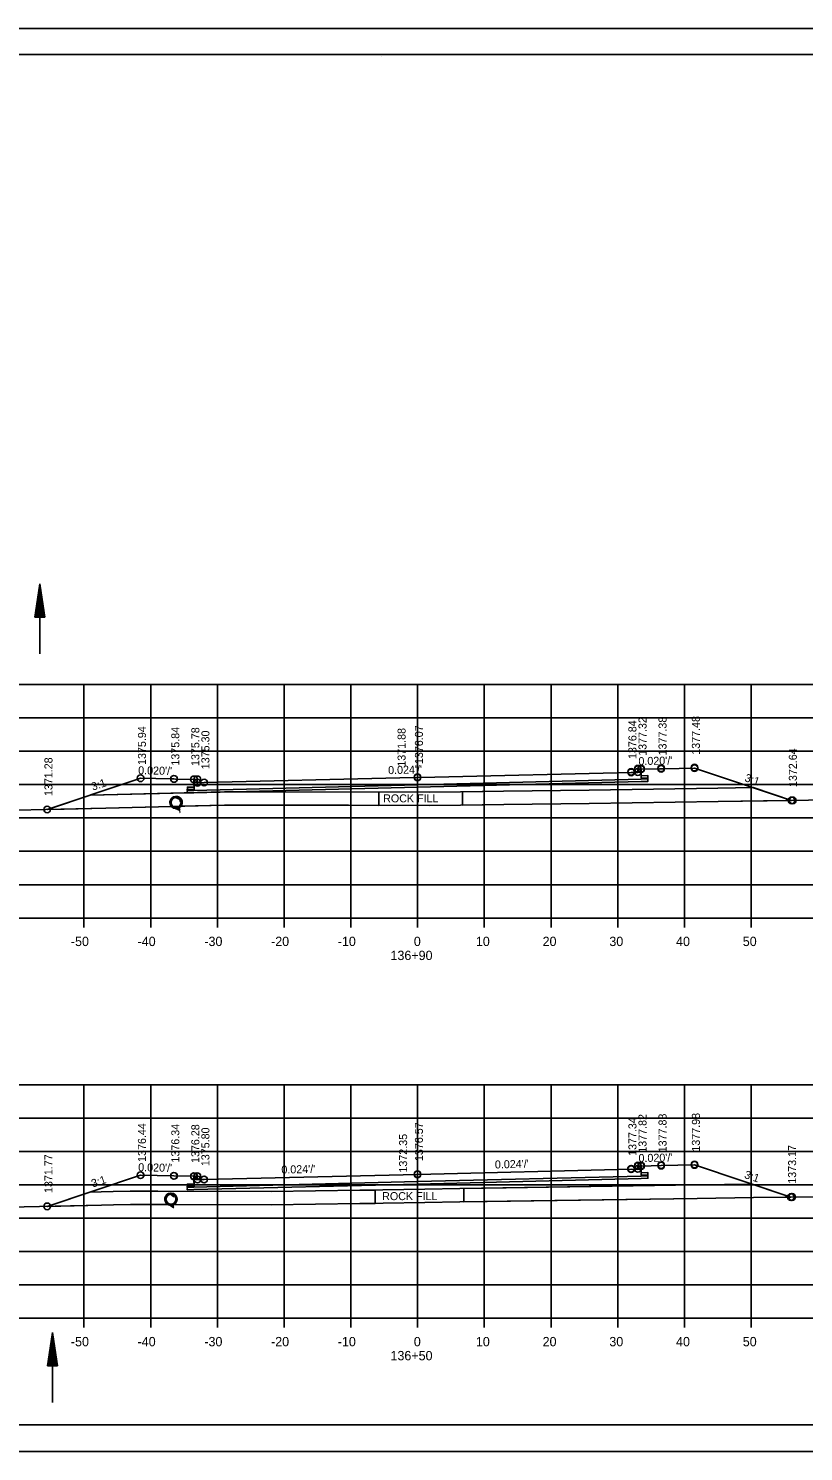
# Model space of a CAD drawing. Extents: x 1374311 to 1383814, y 384102 to 406278.
# Drawn here: x 1381570.3 to 1381686.5, y 388378 to 388591.4 of the extents above; entities that cross this region are included whole.
import ezdxf

# ---------------------------------------------------------------- set-up
doc = ezdxf.new("R2010")
doc.units = 0
for name, color, linetype in [('R_Axis', 7, 'Continuous'), ('R_Axis Annot', 7, 'Continuous'), ('R_Border', 7, 'Continuous'), ('R_Draft', 7, 'Continuous'), ('R_Exist Surface', 7, 'Continuous'), ('R_Fin Surface', 7, 'Continuous'), ('R_Grid', 7, 'Continuous'), ('R_No Plot', 7, 'Continuous'), ('R_Water', 7, 'Continuous'), ('R_Xsect Elev', 7, 'Continuous'), ('R_Xsect Slope', 7, 'Continuous')]:
    doc.layers.add(name, color=color, linetype=linetype)

msp = doc.modelspace()

# ---------------------------------------------------------------- linework, layer by layer
at = {"layer": 'R_Axis'}
for p, q in [((1381488.66, 388458), (1381768.66, 388458)), ((1381578.66, 388456.6), (1381578.66, 388458)), ((1381588.66, 388456.6), (1381588.66, 388458)), ((1381598.66, 388456.6), (1381598.66, 388458)), ((1381608.66, 388456.6), (1381608.66, 388458)), ((1381618.66, 388456.6), (1381618.66, 388458)), ((1381628.66, 388456.6), (1381628.66, 388458)), ((1381638.66, 388456.6), (1381638.66, 388458)), ((1381648.66, 388456.6), (1381648.66, 388458)), ((1381658.66, 388456.6), (1381658.66, 388458)), ((1381668.66, 388456.6), (1381668.66, 388458)), ((1381678.66, 388456.6), (1381678.66, 388458)), ((1381488.66, 388398), (1381768.66, 388398)), ((1381578.66, 388396.6), (1381578.66, 388398)), ((1381588.66, 388396.6), (1381588.66, 388398)), ((1381598.66, 388396.6), (1381598.66, 388398)), ((1381608.66, 388396.6), (1381608.66, 388398)), ((1381618.66, 388396.6), (1381618.66, 388398)), ((1381628.66, 388396.6), (1381628.66, 388398)), ((1381638.66, 388396.6), (1381638.66, 388398)), ((1381648.66, 388396.6), (1381648.66, 388398)), ((1381658.66, 388396.6), (1381658.66, 388398)), ((1381668.66, 388396.6), (1381668.66, 388398)), ((1381678.66, 388396.6), (1381678.66, 388398))]:
    msp.add_line(p, q, dxfattribs=at)
at = {"layer": 'R_Border'}
for p, q in [((1381470.66, 388587.46), (1381786.84, 388587.46)), ((1381623.18, 388587.2), (1381623.18, 388587.2)), ((1381623.18, 388587.2), (1381623.18, 388587.2)), ((1381786.84, 388382), (1381470.66, 388382))]:
    msp.add_line(p, q, dxfattribs=at)
at = {"layer": 'R_Draft'}
for p, q in [((1381571.32, 388503.1), (1381572.07, 388508.1)), ((1381571.45, 388503.1), (1381572.07, 388507.27)), ((1381572.82, 388503.1), (1381572.07, 388508.1)), ((1381572.7, 388503.1), (1381572.07, 388507.27)), ((1381571.58, 388503.1), (1381572.07, 388506.41)), ((1381571.7, 388503.1), (1381572.07, 388505.58)), ((1381572.57, 388503.1), (1381572.07, 388506.41)), ((1381572.45, 388503.1), (1381572.07, 388505.58)), ((1381572.82, 388503.1), (1381571.32, 388503.1)), ((1381571.83, 388503.1), (1381572.07, 388504.73)), ((1381571.96, 388503.1), (1381572.07, 388503.89)), ((1381572.32, 388503.1), (1381572.07, 388504.73)), ((1381572.19, 388503.1), (1381572.07, 388503.89)), ((1381573.21, 388390.86), (1381573.96, 388395.86)), ((1381573.34, 388390.86), (1381573.96, 388395.02)), ((1381573.46, 388390.86), (1381573.96, 388394.16)), ((1381574.71, 388390.86), (1381573.96, 388395.86)), ((1381574.59, 388390.86), (1381573.96, 388395.02)), ((1381574.46, 388390.86), (1381573.96, 388394.16)), ((1381573.59, 388390.86), (1381573.96, 388393.33)), ((1381573.72, 388390.86), (1381573.96, 388392.48)), ((1381574.33, 388390.86), (1381573.96, 388393.33)), ((1381574.2, 388390.86), (1381573.96, 388392.48)), ((1381574.71, 388390.86), (1381573.21, 388390.86)), ((1381573.84, 388390.86), (1381573.96, 388391.65)), ((1381574.08, 388390.86), (1381573.96, 388391.65))]:
    msp.add_line(p, q, dxfattribs=at)
at = {"layer": 'R_Exist Surface'}
for p, q in [((1381592.39, 388476.24), (1381593.08, 388475.94)), ((1381593.08, 388475.69), (1381592.98, 388475.65)), ((1381592.39, 388474.41), (1381593.08, 388474.11)), ((1381593.08, 388473.85), (1381592.98, 388473.82)), ((1381591.63, 388416.76), (1381592.15, 388416.37)), ((1381591.63, 388414.93), (1381592.15, 388414.54))]:
    msp.add_line(p, q, dxfattribs=at)
for points in [[(1381559.46, 388473.96), (1381581.93, 388474.49), (1381599.74, 388474.92), (1381608.42, 388474.91), (1381618.31, 388474.9), (1381630.47, 388474.88), (1381635.11, 388474.93), (1381641.57, 388475.03), (1381654.38, 388475.19), (1381673.7, 388475.47), (1381687.26, 388475.68), (1381702.62, 388475.9), (1381704.36, 388475.93), (1381704.57, 388475.93), (1381721.15, 388476.2), (1381723.51, 388476.24), (1381739.25, 388476.4), (1381742.02, 388476.45), (1381755.88, 388476.6), (1381759.85, 388476.68), (1381768.66, 388476.78)], [(1381544.12, 388414.17), (1381581.28, 388414.95), (1381583.08, 388414.99), (1381585.62, 388415.04), (1381589.73, 388415.05), (1381606.71, 388414.99), (1381620.02, 388415.2), (1381623.49, 388415.24), (1381629.77, 388415.37), (1381635, 388415.44), (1381670.54, 388415.98), (1381679.01, 388416.1), (1381688.4, 388416.22), (1381698.13, 388416.37), (1381706.03, 388416.47), (1381717.22, 388416.57), (1381724.4, 388416.67), (1381736.85, 388416.77), (1381742.19, 388416.85), (1381755.79, 388416.95), (1381759.43, 388417), (1381768.66, 388417.06)]]:
    msp.add_lwpolyline(points, dxfattribs=at)
for centre in [(1381592.46, 388475.32), (1381591.7, 388415.84)]:
    msp.add_circle(centre, 0.917, dxfattribs=at)
at = {"layer": 'R_Fin Surface'}
for p, q in [((1381684.7, 388475.64), (1381678.96, 388477.55)), ((1381579.59, 388476.43), (1381573.62, 388474.44)), ((1381594.15, 388476.78), (1381579.59, 388476.43)), ((1381592.39, 388476.24), (1381592.4, 388476.24)), ((1381622.85, 388476.89), (1381622.85, 388474.89)), ((1381622.85, 388474.89), (1381622.85, 388476.89)), ((1381635.37, 388476.94), (1381635.37, 388474.94)), ((1381635.37, 388476.94), (1381635.37, 388474.94)), ((1381635.37, 388474.94), (1381641.57, 388475.03)), ((1381673.7, 388475.47), (1381684.7, 388475.64)), ((1381618.31, 388474.9), (1381622.85, 388474.89)), ((1381635.58, 388417.45), (1381635.58, 388415.45)), ((1381635.58, 388417.45), (1381635.58, 388415.45)), ((1381591.63, 388416.76), (1381591.63, 388416.76)), ((1381622.29, 388417.22), (1381622.29, 388415.22)), ((1381622.29, 388415.22), (1381622.29, 388417.22)), ((1381635.58, 388415.45), (1381670.54, 388415.98)), ((1381592.14, 388415.04), (1381606.71, 388414.99)), ((1381606.71, 388414.99), (1381620.02, 388415.2)), ((1381620.02, 388415.2), (1381622.29, 388415.22))]:
    msp.add_line(p, q, dxfattribs=at)
for points in [[(1381573.14, 388474.28), (1381586, 388478.57), (1381587.15, 388478.95), (1381591.74, 388478.86), (1381592.15, 388478.85), (1381592.39, 388478.84), (1381595.15, 388478.79), (1381595.6, 388478.79), (1381595.65, 388478.79), (1381595.65, 388478.75), (1381595.66, 388478.29), (1381595.74, 388478.29), (1381596.66, 388478.31), (1381626.02, 388479.01), (1381628.66, 388479.08), (1381631.24, 388479.14), (1381660.66, 388479.84), (1381660.74, 388479.84), (1381661.66, 388479.82), (1381661.66, 388480.28), (1381661.67, 388480.32), (1381661.71, 388480.32), (1381662.17, 388480.32), (1381664.92, 388480.38), (1381665.17, 388480.38), (1381665.57, 388480.39), (1381670.17, 388480.48), (1381671.34, 388480.09), (1381684.7, 388475.64)], [(1381662.17, 388480.03), (1381662.18, 388478.95), (1381663.18, 388478.99), (1381663.17, 388478.49), (1381662.17, 388478.46), (1381628.66, 388477.62), (1381595.15, 388476.78), (1381594.15, 388476.76), (1381594.16, 388477.26), (1381595.16, 388477.27), (1381595.15, 388478.43)], [(1381579.59, 388476.43), (1381599.72, 388476.92), (1381608.42, 388476.91), (1381630.47, 388476.88), (1381635.09, 388476.93), (1381641.54, 388477.03), (1381654.36, 388477.19), (1381673.67, 388477.47), (1381678.96, 388477.55)], [(1381678.96, 388477.55), (1381673.67, 388477.47), (1381654.36, 388477.19), (1381641.54, 388477.03), (1381635.37, 388476.94)], [(1381592.39, 388476.24), (1381592.39, 388476.24)], [(1381600.41, 388476.92), (1381595.15, 388476.78), (1381594.15, 388476.76), (1381594.15, 388476.78)], [(1381622.85, 388476.89), (1381608.42, 388476.91), (1381600.41, 388476.92)], [(1381641.57, 388475.03), (1381654.38, 388475.19), (1381673.7, 388475.47)], [(1381573.64, 388474.29), (1381581.93, 388474.49), (1381591.77, 388474.72)], [(1381593.18, 388474.76), (1381599.74, 388474.92), (1381608.42, 388474.91), (1381618.31, 388474.9)], [(1381573.14, 388414.78), (1381587.15, 388419.44), (1381592.15, 388419.34), (1381595.15, 388419.28), (1381595.65, 388419.28), (1381595.66, 388418.78), (1381596.66, 388418.8), (1381628.66, 388419.57), (1381660.66, 388420.34), (1381661.66, 388420.32), (1381661.67, 388420.82), (1381662.17, 388420.82), (1381665.17, 388420.88), (1381670.17, 388420.98), (1381684.59, 388416.17)], [(1381662.17, 388420.52), (1381662.18, 388419.44), (1381663.18, 388419.48), (1381663.17, 388418.98), (1381662.17, 388418.96), (1381628.66, 388418.12), (1381595.15, 388417.28), (1381594.15, 388417.26), (1381594.16, 388417.76), (1381595.16, 388417.77), (1381595.15, 388418.92)], [(1381579.54, 388416.91), (1381581.24, 388416.95), (1381583.03, 388416.99), (1381585.59, 388417.04), (1381589.73, 388417.05), (1381606.7, 388416.99), (1381620, 388417.2), (1381623.46, 388417.24), (1381629.74, 388417.37), (1381634.97, 388417.44), (1381670.51, 388417.98), (1381678.82, 388418.1)], [(1381678.82, 388418.1), (1381670.51, 388417.98), (1381635.58, 388417.45)], [(1381670.54, 388415.98), (1381679.01, 388416.1), (1381684.59, 388416.17), (1381678.82, 388418.1)], [(1381579.54, 388416.91), (1381573.14, 388414.78), (1381581.28, 388414.95), (1381583.08, 388414.99), (1381585.62, 388415.04)], [(1381622.29, 388417.22), (1381620, 388417.2), (1381606.7, 388416.99), (1381589.73, 388417.05), (1381585.59, 388417.04), (1381583.03, 388416.99), (1381581.24, 388416.95), (1381579.54, 388416.91)], [(1381579.54, 388416.91), (1381579.54, 388416.91)], [(1381591.63, 388416.76), (1381591.63, 388416.76)], [(1381585.62, 388415.04), (1381589.73, 388415.05), (1381591.26, 388415.04)]]:
    msp.add_lwpolyline(points, dxfattribs=at)
for centre, radius, start, end in [((1381592.46, 388475.32), 0.917, 94.3096, 220.8594), ((1381592.46, 388475.32), 0.917, 321.9142, 94.0009), ((1381573.14, 388474.28), 0.5, 1.3996, 18.4351), ((1381591.7, 388415.84), 0.917, 94.3096, 241.0185), ((1381591.7, 388415.84), 0.917, 298.6241, 94.1246)]:
    msp.add_arc(centre, radius, start, end, dxfattribs=at)
at = {"layer": 'R_Grid'}
for p, q in [((1381488.66, 388493), (1381768.66, 388493)), ((1381578.66, 388458), (1381578.66, 388493)), ((1381588.66, 388458), (1381588.66, 388493)), ((1381598.66, 388458), (1381598.66, 388493)), ((1381608.66, 388458), (1381608.66, 388493)), ((1381618.66, 388458), (1381618.66, 388493)), ((1381628.66, 388458), (1381628.66, 388493)), ((1381638.66, 388458), (1381638.66, 388493)), ((1381648.66, 388458), (1381648.66, 388493)), ((1381658.66, 388458), (1381658.66, 388493)), ((1381668.66, 388458), (1381668.66, 388493)), ((1381678.66, 388458), (1381678.66, 388493)), ((1381488.66, 388488), (1381768.66, 388488)), ((1381488.66, 388483), (1381768.66, 388483)), ((1381488.66, 388478), (1381768.66, 388478)), ((1381488.66, 388473), (1381768.66, 388473)), ((1381488.66, 388468), (1381768.66, 388468)), ((1381488.66, 388463), (1381768.66, 388463)), ((1381488.66, 388458), (1381768.66, 388458)), ((1381488.66, 388433), (1381768.66, 388433)), ((1381578.66, 388398), (1381578.66, 388433)), ((1381588.66, 388398), (1381588.66, 388433)), ((1381598.66, 388398), (1381598.66, 388433)), ((1381608.66, 388398), (1381608.66, 388433)), ((1381618.66, 388398), (1381618.66, 388433)), ((1381628.66, 388398), (1381628.66, 388433)), ((1381638.66, 388398), (1381638.66, 388433)), ((1381648.66, 388398), (1381648.66, 388433)), ((1381658.66, 388398), (1381658.66, 388433)), ((1381668.66, 388398), (1381668.66, 388433)), ((1381678.66, 388398), (1381678.66, 388433)), ((1381488.66, 388428), (1381768.66, 388428)), ((1381488.66, 388423), (1381768.66, 388423)), ((1381488.66, 388418), (1381768.66, 388418)), ((1381488.66, 388413), (1381768.66, 388413)), ((1381488.66, 388408), (1381768.66, 388408)), ((1381488.66, 388403), (1381768.66, 388403)), ((1381488.66, 388398), (1381768.66, 388398))]:
    msp.add_line(p, q, dxfattribs=at)
at = {"layer": 'R_No Plot'}
for p, q in [((1381458.26, 388591.36), (1381791.59, 388591.36)), ((1381458.26, 388378.03), (1381791.59, 388378.03))]:
    msp.add_line(p, q, dxfattribs=at)
for points in [[(1381458.25, 388591.36), (1381791.59, 388591.36), (1381791.59, 388378.02), (1381458.25, 388378.02)], [(1381704.58, 388587.46), (1381704.58, 388577.58), (1381740.31, 388577.58), (1381740.31, 388574.66), (1381763.51, 388574.66), (1381763.51, 388551.45), (1381786.84, 388551.45), (1381786.84, 388382), (1381470.66, 388382), (1381470.66, 388587.46)], [(1381573.14, 388474.28), (1381581.93, 388474.49), (1381599.74, 388474.92), (1381608.42, 388474.91), (1381618.31, 388474.9), (1381630.47, 388474.88), (1381635.11, 388474.93), (1381641.57, 388475.03), (1381654.38, 388475.19), (1381673.7, 388475.47), (1381684.7, 388475.64), (1381671.34, 388480.09), (1381670.17, 388480.48), (1381665.57, 388480.39), (1381665.17, 388480.38), (1381664.92, 388480.38), (1381662.17, 388480.32), (1381662.18, 388479.31), (1381663.18, 388479.35), (1381663.17, 388478.85), (1381662.17, 388478.82), (1381628.66, 388477.98), (1381595.15, 388477.14), (1381594.15, 388477.12), (1381594.16, 388477.62), (1381595.16, 388477.63), (1381595.15, 388478.79), (1381592.39, 388478.84), (1381592.15, 388478.85), (1381591.74, 388478.86), (1381587.15, 388478.95), (1381586, 388478.57)], [(1381573.14, 388414.78), (1381581.28, 388414.95), (1381583.08, 388414.99), (1381585.62, 388415.04), (1381589.73, 388415.05), (1381606.71, 388414.99), (1381620.02, 388415.2), (1381623.49, 388415.24), (1381629.77, 388415.37), (1381635, 388415.44), (1381670.54, 388415.98), (1381679.01, 388416.1), (1381684.59, 388416.17), (1381670.17, 388420.98), (1381665.17, 388420.88), (1381662.17, 388420.82), (1381662.18, 388419.8), (1381663.18, 388419.84), (1381663.17, 388419.34), (1381662.17, 388419.32), (1381628.66, 388418.48), (1381595.15, 388417.64), (1381594.15, 388417.62), (1381594.16, 388418.12), (1381595.16, 388418.13), (1381595.15, 388419.28), (1381592.15, 388419.34), (1381587.15, 388419.44)]]:
    msp.add_lwpolyline(points, close=True, dxfattribs=at)
for centre in [(1381587.15, 388478.95), (1381587.15, 388478.95), (1381587.15, 388478.95), (1381592.15, 388478.85), (1381592.15, 388478.85), (1381592.15, 388478.85), (1381595.15, 388478.79), (1381595.15, 388478.79), (1381595.15, 388478.79), (1381595.65, 388478.79), (1381595.65, 388478.79), (1381595.65, 388478.79), (1381628.66, 388479.11), (1381628.66, 388479.11), (1381628.66, 388479.08), (1381660.66, 388479.91), (1381660.66, 388479.91), (1381660.66, 388479.84), (1381661.66, 388479.89), (1381661.67, 388480.39), (1381661.67, 388480.39), (1381661.67, 388480.32), (1381662.17, 388480.39), (1381662.17, 388480.39), (1381662.17, 388480.32), (1381665.17, 388480.45), (1381665.17, 388480.45), (1381665.17, 388480.38), (1381670.17, 388480.55), (1381670.17, 388480.55), (1381670.17, 388480.48), (1381595.66, 388478.29), (1381596.66, 388478.31), (1381596.66, 388478.31), (1381596.66, 388478.31), (1381684.7, 388475.64), (1381684.88, 388475.64), (1381684.88, 388475.64), (1381573.14, 388474.28), (1381573.14, 388474.28), (1381573.14, 388474.28), (1381573.14, 388474.28), (1381573.14, 388474.28), (1381573.14, 388474.28), (1381587.14, 388419.45), (1381587.15, 388419.45), (1381587.15, 388419.44), (1381592.14, 388419.35), (1381592.15, 388419.35), (1381592.15, 388419.34), (1381595.14, 388419.29), (1381595.15, 388419.29), (1381595.15, 388419.28), (1381595.64, 388419.29), (1381595.65, 388419.29), (1381595.65, 388419.28), (1381628.65, 388419.61), (1381628.66, 388419.61), (1381628.66, 388419.57), (1381660.65, 388420.41), (1381660.66, 388420.41), (1381660.66, 388420.34), (1381661.66, 388420.89), (1381661.66, 388420.39), (1381661.67, 388420.89), (1381661.67, 388420.82), (1381662.16, 388420.89), (1381662.17, 388420.89), (1381662.17, 388420.82), (1381665.16, 388420.95), (1381665.17, 388420.95), (1381665.17, 388420.88), (1381670.16, 388421.05), (1381670.17, 388421.05), (1381670.17, 388420.98), (1381595.66, 388418.79), (1381596.65, 388418.81), (1381596.66, 388418.81), (1381596.66, 388418.8), (1381573.14, 388414.78), (1381573.14, 388414.78), (1381573.14, 388414.78), (1381573.14, 388414.78), (1381573.14, 388414.78), (1381573.14, 388414.78), (1381684.59, 388416.17), (1381684.77, 388416.18), (1381684.78, 388416.18)]:
    msp.add_circle(centre, 0.5, dxfattribs=at)
at = {"layer": 'R_Water'}
for p, q in [((1381572.07, 388497.6), (1381572.07, 388508.1)), ((1381592.39, 388476.07), (1381593.08, 388475.77)), ((1381593.08, 388475.52), (1381592.98, 388475.48)), ((1381592.39, 388474.57), (1381593.08, 388474.27)), ((1381593.08, 388474.02), (1381592.98, 388473.98)), ((1381591.63, 388416.59), (1381592.15, 388416.2)), ((1381591.63, 388415.09), (1381592.15, 388414.7)), ((1381573.96, 388385.35), (1381573.96, 388395.86))]:
    msp.add_line(p, q, dxfattribs=at)
for centre in [(1381592.46, 388475.32), (1381591.7, 388415.84)]:
    msp.add_circle(centre, 0.75, dxfattribs=at)

# ---------------------------------------------------------------- texts
at = {"layer": 'R_Axis Annot'}
for s, p in [('-50', (1381576.7, 388453.8)), ('-40', (1381586.7, 388453.8)), ('-30', (1381596.7, 388453.8)), ('-20', (1381606.7, 388453.8)), ('-10', (1381616.7, 388453.8)), ('0', (1381628.1, 388453.8)), ('10', (1381637.4, 388453.8)), ('20', (1381647.4, 388453.8)), ('30', (1381657.4, 388453.8)), ('40', (1381667.4, 388453.8)), ('50', (1381677.4, 388453.8)), ('136+90', (1381624.6, 388451.7)), ('-50', (1381576.7, 388393.8)), ('-40', (1381586.7, 388393.8)), ('-30', (1381596.7, 388393.8)), ('-20', (1381606.7, 388393.8)), ('-10', (1381616.7, 388393.8)), ('0', (1381628.1, 388393.8)), ('10', (1381637.4, 388393.8)), ('20', (1381647.4, 388393.8)), ('30', (1381657.4, 388393.8)), ('40', (1381667.4, 388393.8)), ('50', (1381677.4, 388393.8)), ('136+50', (1381624.6, 388391.7))]:
    msp.add_text(s, height=1.4, dxfattribs=at).set_placement(p)
at = {"layer": 'R_Fin Surface'}
for p in [(1381623.5, 388475.34), (1381623.35, 388415.71)]:
    msp.add_text('ROCK FILL', height=1.2, dxfattribs=at).set_placement(p)
at = {"layer": 'R_Xsect Elev'}
for s, p in [('1377.32', (1381662.97, 388482.32)), ('1377.38', (1381665.97, 388482.38)), ('1377.48', (1381670.97, 388482.48)), ('1375.94', (1381587.95, 388480.95)), ('1375.84', (1381592.95, 388480.85)), ('1375.78', (1381595.95, 388480.79)), ('1375.30', (1381597.46, 388480.31)), ('1371.88', (1381626.86, 388480.69)), ('1376.07', (1381629.46, 388481.08)), ('1376.84', (1381661.46, 388481.84)), ('1371.28', (1381573.94, 388476.28)), ('1372.64', (1381685.5, 388477.64)), ('1377.34', (1381661.46, 388422.34)), ('1377.82', (1381662.97, 388422.82)), ('1377.88', (1381665.97, 388422.88)), ('1377.98', (1381670.97, 388422.98)), ('1376.44', (1381587.95, 388421.44)), ('1376.34', (1381592.95, 388421.34)), ('1376.28', (1381595.95, 388421.28)), ('1375.80', (1381597.46, 388420.8)), ('1376.57', (1381629.46, 388421.57)), ('1372.35', (1381627.09, 388419.84)), ('1373.17', (1381685.39, 388418.17)), ('1371.77', (1381573.94, 388416.78))]:
    msp.add_text(s, height=1.2, rotation=90, dxfattribs=at).set_placement(p)
at = {"layer": 'R_Xsect Slope'}
for s, rotation, p in [("0.020'/'", 1.1458, (1381661.77, 388480.92)), ("0.020'/'", 358.8542, (1381586.78, 388479.56)), ("0.024'/'", 1.3748, (1381624.26, 388479.57)), ('3:1', 341.5651, (1381677.59, 388478.54)), ('3:1', 18.4349, (1381579.99, 388477.09)), ("0.024'/'", 1.3748, (1381640.26, 388420.45)), ("0.020'/'", 1.1458, (1381661.78, 388421.41)), ("0.020'/'", 358.8542, (1381586.78, 388420.05)), ("0.024'/'", 1.3748, (1381608.26, 388419.68)), ('3:1', 341.5651, (1381677.54, 388419.05)), ('3:1', 18.4349, (1381579.99, 388417.59))]:
    msp.add_text(s, height=1.2, rotation=rotation, dxfattribs=at).set_placement(p)

doc.saveas('drawing.dxf')
